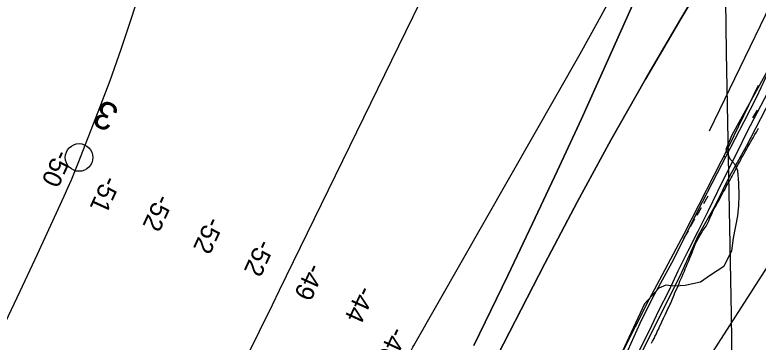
# Model space of a CAD drawing. Extents: x 3930721 to 3950824, y 220441 to 242861.
# Drawn here: x 3939511 to 3940855, y 227422 to 228013 of the extents above; entities that cross this region are included whole.
import ezdxf

# ---------------------------------------------------------------- set-up
doc = ezdxf.new("R2010")
doc.units = 0
for name, color, linetype in [('V-GRID-MAJR', 7, 'Continuous'), ('V-RIVR-EDGE', 7, 'Continuous'), ('V-RIVR-IDEN', 7, 'Continuous'), ('V-RIVR-JETY', 7, 'Continuous'), ('V-RIVR-MILE', 7, 'Continuous'), ('V-RIVR-RANG', 7, 'Continuous'), ('V-RRAP-FSHR', 7, 'Continuous'), ('V-TOPO-DPTH', 7, 'Continuous'), ('V-TOPO-MAJR', 7, 'Continuous'), ('V-TOPO-MINR', 7, 'Continuous'), ('V-TOPO-SHOR', 7, 'Continuous'), ('V-UTIL-LINE', 7, 'Continuous'), ('V-WETL-SWMP', 7, 'Continuous')]:
    doc.layers.add(name, color=color, linetype=linetype)

msp = doc.modelspace()

# ---------------------------------------------------------------- linework, layer by layer
at = {"layer": 'V-GRID-MAJR'}
msp.add_spline([(3940914.4, 221486.3), (3940866.3, 224158.2), (3940756.9, 230218.1), (3940647.6, 236278.1), (3940604.7, 238656.8)], degree=3, dxfattribs=at)
at = {"layer": 'V-RIVR-EDGE'}
msp.add_lwpolyline([(3940939, 228034.7), (3940807.6, 227796.2), (3940796.6, 227770.2), (3940803.6, 227753.6), (3940812.3, 227744.2), (3940817.8, 227732.4), (3940819.4, 227709.6), (3940820.2, 227687.5), (3940819.4, 227669.4), (3940817.8, 227650.5), (3940809.9, 227610.4), (3940806.8, 227587.6), (3940792.6, 227559.2), (3940769, 227543.5), (3940750.9, 227530.9), (3940723.3, 227524.6), (3940705.2, 227523.8), (3940687.9, 227525.4), (3940675.3, 227519.9), (3940649.4, 227491.5), (3940480.9, 227129.4)], dxfattribs=at)
at = {"layer": 'V-RIVR-JETY'}
for points in [[(3940975.3, 228056.9), (3940948.8, 227998.4), (3940919.5, 227941.1), (3940876.7, 227859.2), (3940833.1, 227775.8), (3940803.3, 227722), (3940777.1, 227669.1), (3940746.6, 227615.3), (3940716.2, 227548.1), (3940676.2, 227467.1), (3940639.1, 227394.4), (3940613.8, 227333.6), (3940588, 227284.2), (3940566.5, 227232.8), (3940530.6, 227163.6), (3940492.1, 227081.5), (3940457.5, 227003.6), (3940435.5, 226958.6), (3940412, 226909.2)], [(3940620.1, 227408.4), (3940641.6, 227456.9), (3940664.8, 227502.8), (3940702.6, 227572), (3940745.4, 227658.5), (3940780.9, 227726.9), (3940829.9, 227821), (3940852.6, 227865.7), (3940876.1, 227915.9)]]:
    msp.add_lwpolyline(points, dxfattribs=at)
at = {"layer": 'V-RIVR-MILE'}
msp.add_circle((3939627.5, 227755.9), 25, dxfattribs=at)
at = {"layer": 'V-RRAP-FSHR'}
msp.add_lwpolyline([(3940640.5, 227407.7), (3940658.5, 227443.6), (3940675.6, 227479.6), (3940693.8, 227515.6), (3940710.6, 227551.5), (3940728.5, 227587.3), (3940746.3, 227623.1), (3940764.7, 227658.9), (3940781.9, 227694.8), (3940799.7, 227730.6), (3940817.5, 227766.4), (3940835.3, 227802.2), (3940853.6, 227837.8), (3940872.3, 227873.3)], dxfattribs=at)
at = {"layer": 'V-TOPO-DPTH'}
for points in [[(3940340.8, 227416.1), (3940402.2, 227542.7), (3940447.3, 227636.8), (3940491.9, 227731.1), (3940535.5, 227825.8), (3940578.5, 227920.9), (3940734.2, 228269.4)], [(3940734.2, 228269.4), (3940578.5, 227920.9), (3940535.5, 227825.8), (3940491.9, 227731.1), (3940447.3, 227636.8), (3940402.2, 227542.7), (3940340.8, 227416.1)], [(3940816.6, 228175.7), (3940715.1, 228006.3), (3940651.1, 227897.2), (3940588.6, 227787.3), (3940528.1, 227676.2), (3940469.1, 227564.4), (3940362.4, 227357.4), (3940357, 227346.9), (3940351.8, 227336.5), (3940346.7, 227325.9), (3940341.6, 227315.3), (3940285, 227194.8), (3940251.8, 227123.8), (3940218.8, 227052.7), (3940186.1, 226981.6), (3940153.6, 226910.3), (3939964.5, 226493.2), (3939952.2, 226466), (3939939.8, 226438.8), (3939927.4, 226411.6), (3939914.9, 226384.5), (3939698.1, 225912.3)], [(3939570.3, 225876.8), (3939810.4, 226486.5), (3939910.3, 226761), (3939959.3, 226868.2), (3940009.4, 226974.8), (3940061.2, 227080.7), (3940114.1, 227186), (3940218.2, 227388.8), (3940219.9, 227392.3), (3940221.7, 227395.8), (3940223.4, 227399.2), (3940225.1, 227402.7), (3940226.9, 227406.2), (3940228.7, 227409.6), (3940230.5, 227413.1), (3940232.4, 227416.5), (3940533.1, 227943.2), (3940564.5, 227999.5), (3940595.1, 228056.1)], [(3939570.3, 225876.8), (3939810.4, 226486.5), (3939910.3, 226761), (3939959.3, 226868.2), (3940009.4, 226974.8), (3940061.2, 227080.7), (3940114.1, 227186), (3940218.2, 227388.8), (3940219.9, 227392.3), (3940221.7, 227395.8), (3940223.4, 227399.2), (3940225.1, 227402.7), (3940226.9, 227406.2), (3940228.7, 227409.6), (3940230.5, 227413.1), (3940232.4, 227416.5), (3940533.1, 227943.2), (3940564.5, 227999.5), (3940595.1, 228056.1)]]:
    msp.add_lwpolyline(points, dxfattribs=at)
at = {"layer": 'V-TOPO-MAJR'}
for points in [[(3939106.3, 225742.9), (3939376.3, 226272.7), (3939407.3, 226333.6), (3939438.1, 226394.6), (3939468.7, 226455.7), (3939499.2, 226516.8), (3939549.3, 226617.6), (3939554.7, 226628.4), (3939560, 226639.1), (3939565.3, 226649.9), (3939570.6, 226660.7), (3939717.3, 226961.4), (3939764.6, 227058.2), (3939812, 227155), (3939859.5, 227251.8), (3939907.1, 227348.6), (3939976.8, 227490.1), (3939989.5, 227516.1), (3940002.3, 227542), (3940015, 227568), (3940027.7, 227594), (3940294.5, 228140.7)], [(3939740.2, 228065.9), (3939722.1, 228008.4), (3939703.1, 227951.2), (3939682.8, 227894.5), (3939661.6, 227838), (3939625.4, 227745), (3939619.4, 227730), (3939613.2, 227715.1), (3939606.8, 227700.2), (3939600.1, 227685.5), (3939551.8, 227581), (3939520.6, 227514.1), (3939489.2, 227447.4)]]:
    msp.add_lwpolyline(points, dxfattribs=at)
at = {"layer": 'V-TOPO-MINR'}
for points in [[(3940766.8, 227803.9), (3940932.6, 228146.5), (3940939.7, 228161), (3940947, 228175.5), (3940954.4, 228189.9), (3940961.9, 228204.2), (3941144.3, 228546.7)], [(3940340.8, 227416.1), (3940402.2, 227542.7), (3940447.3, 227636.8), (3940491.9, 227731.1), (3940535.5, 227825.8), (3940578.5, 227920.9), (3940734.2, 228269.4)], [(3939698.1, 225912.3), (3939914.9, 226384.5), (3939927.4, 226411.6), (3939939.8, 226438.8), (3939952.2, 226466), (3939964.5, 226493.2), (3940153.6, 226910.3), (3940186.1, 226981.6), (3940218.8, 227052.7), (3940251.8, 227123.8), (3940285, 227194.8), (3940341.6, 227315.3), (3940346.7, 227325.9), (3940351.8, 227336.5), (3940357, 227346.9), (3940362.4, 227357.4), (3940469.1, 227564.4), (3940528.1, 227676.2), (3940588.6, 227787.3), (3940651.1, 227897.2), (3940715.1, 228006.3), (3940816.6, 228175.7)], [(3939570.3, 225876.8), (3939810.4, 226486.5), (3939910.3, 226761), (3939959.3, 226868.2), (3940009.4, 226974.8), (3940061.2, 227080.7), (3940114.1, 227186), (3940218.2, 227388.8), (3940219.9, 227392.3), (3940221.7, 227395.8), (3940223.4, 227399.2), (3940225.1, 227402.7), (3940226.9, 227406.2), (3940228.7, 227409.6), (3940230.5, 227413.1), (3940232.4, 227416.5), (3940533.1, 227943.2), (3940564.5, 227999.5), (3940595.1, 228056.1)]]:
    msp.add_lwpolyline(points, dxfattribs=at)
at = {"layer": 'V-TOPO-SHOR'}
for points in [[(3940776.5, 227665.3), (3940778.2, 227668.1), (3940781.3, 227673.8), (3940785.1, 227680.1), (3940786.8, 227683.6), (3940789.2, 227688.2), (3940791.2, 227692.4), (3940793, 227695.2), (3940795, 227698.7), (3940797.4, 227703.3), (3940799.1, 227706.5), (3940801.9, 227711.4), (3940803.6, 227714.5), (3940806.4, 227719.1), (3940807.7, 227722.3), (3940810.1, 227726.8), (3940812.5, 227731.1), (3940813.9, 227733.9), (3940815.9, 227738.1), (3940819.7, 227744.4), (3940821.1, 227747.2), (3940823.5, 227751.8), (3940824.9, 227755), (3940826.6, 227757.8), (3940829, 227761.6), (3940832.8, 227768.7), (3940834.5, 227771.5), (3940836.2, 227775.3), (3940839.6, 227781.3), (3940841.3, 227783.8), (3940843.4, 227788), (3940845.8, 227791.2), (3940849.2, 227797.5), (3940851.7, 227801.4), (3940853.7, 227805.2), (3940855.4, 227808.7)], [(3940662.1, 227420.3), (3940664.2, 227424.1), (3940666.9, 227429), (3940668.3, 227432.4), (3940671.1, 227437.7), (3940672.4, 227441.5), (3940675.2, 227446.7), (3940676.6, 227450.4), (3940678.9, 227455.2), (3940681, 227459.3), (3940684.1, 227465.9), (3940687.2, 227472.9), (3940689.9, 227478.1), (3940691.6, 227482.5), (3940693.3, 227485.5), (3940695.4, 227490.1), (3940696.8, 227492.8), (3940698.8, 227497.6), (3940699.9, 227500.6), (3940701.9, 227504.6), (3940703.3, 227507.7), (3940704.6, 227511.8), (3940707.7, 227518.5), (3940710.1, 227524.1), (3940712.2, 227528.6), (3940713.5, 227532.4), (3940715.9, 227537.6), (3940717.3, 227540.7), (3940719.3, 227545.9), (3940721.7, 227550.8), (3940723.1, 227554.7), (3940725.5, 227559.8), (3940726.8, 227563.3), (3940728.9, 227568.2), (3940730.3, 227571.2), (3940732.3, 227576.1), (3940734.7, 227581.3), (3940735.7, 227584.2), (3940737.1, 227587.7), (3940738.1, 227591.2), (3940739.5, 227594), (3940741.2, 227598.6), (3940742.5, 227601.7), (3940745.3, 227606.6), (3940748, 227611.6), (3940750.4, 227615.8), (3940752.1, 227618.6), (3940755.2, 227623.9), (3940759.4, 227629.5), (3940761.1, 227632), (3940762.8, 227635.5), (3940765.5, 227641.8), (3940767.6, 227646.4), (3940769, 227649.2), (3940771, 227653.7), (3940772.7, 227656.9), (3940775.1, 227661.8), (3940776.5, 227665.3)]]:
    msp.add_lwpolyline(points, dxfattribs=at)
at = {"layer": 'V-UTIL-LINE'}
msp.add_lwpolyline([(3947453.8, 235874.4), (3945931.1, 235655.1), (3945509.1, 234777.7), (3940428.6, 226869.1), (3939084.6, 223621.7)], dxfattribs=at)
at = {"layer": 'V-WETL-SWMP'}
for p, q in [((3940852.9, 227841.2), (3940845, 227827.3)), ((3940792.6, 227758.6), (3940796, 227756.7)), ((3940764, 227685.9), (3940756, 227672)), ((3940752, 227665.1), (3940744.1, 227651.2)), ((3940740.1, 227644.3), (3940732.2, 227630.4)), ((3940728.2, 227623.4), (3940720.2, 227609.6))]:
    msp.add_line(p, q, dxfattribs=at)
for points in [[(3940854.9, 227885.8), (3940801.7, 227776.3), (3940720.6, 227617.7), (3940657.5, 227498.7), (3940607.6, 227400.2)], [(3940728.9, 227568.2), (3940730.3, 227571.2), (3940732.3, 227576.1), (3940734.7, 227581.3), (3940735.7, 227584.2), (3940737.1, 227587.7), (3940738.1, 227591.2), (3940739.5, 227594), (3940741.2, 227598.6), (3940742.5, 227601.7), (3940748, 227611.6), (3940750.4, 227615.8), (3940752.1, 227618.6), (3940755.2, 227623.9), (3940759.4, 227629.5), (3940761.1, 227632), (3940762.8, 227635.5), (3940765.5, 227641.8), (3940767.6, 227646.4), (3940769, 227649.2), (3940771, 227653.7), (3940772.7, 227656.9), (3940775.1, 227661.8), (3940776.5, 227665.3), (3940778.2, 227668.1), (3940781.3, 227673.8), (3940785.1, 227680.1), (3940786.8, 227683.6), (3940789.2, 227688.2), (3940791.2, 227692.4), (3940793, 227695.2), (3940795, 227698.7), (3940797.4, 227703.3), (3940799.1, 227706.5), (3940801.9, 227711.4), (3940803.6, 227714.5), (3940806.4, 227719.1), (3940807.7, 227722.3), (3940810.1, 227726.8), (3940812.5, 227731.1), (3940815.9, 227738.1), (3940819.7, 227744.4), (3940821.1, 227747.2), (3940823.5, 227751.8), (3940824.9, 227755), (3940826.6, 227757.8), (3940829, 227761.6), (3940832.8, 227768.7), (3940834.5, 227771.5), (3940836.2, 227775.3), (3940839.6, 227781.3), (3940841.3, 227783.8), (3940843.4, 227788), (3940845.8, 227791.2), (3940849.2, 227797.5), (3940851.7, 227801.4), (3940853.7, 227805.2), (3940855.4, 227808.7)], [(3940662.1, 227420.3), (3940664.2, 227424.1), (3940666.9, 227429), (3940668.3, 227432.4), (3940671.1, 227437.7), (3940672.4, 227441.5), (3940675.2, 227446.7), (3940676.6, 227450.4), (3940678.9, 227455.2), (3940681, 227459.3), (3940684.1, 227465.9), (3940687.2, 227472.9), (3940689.9, 227478.1), (3940691.6, 227482.5), (3940693.3, 227485.5), (3940695.4, 227490.1), (3940696.8, 227492.8), (3940698.8, 227497.6), (3940699.9, 227500.6), (3940701.9, 227504.6), (3940703.3, 227507.7), (3940704.6, 227511.8), (3940707.7, 227518.5), (3940710.1, 227524.1), (3940712.2, 227528.6), (3940713.5, 227532.4), (3940715.9, 227537.6), (3940717.3, 227540.7), (3940719.3, 227545.9), (3940721.7, 227550.8), (3940723.1, 227554.7), (3940725.5, 227559.8), (3940726.8, 227563.3), (3940728.9, 227568.2)]]:
    msp.add_lwpolyline(points, dxfattribs=at)

# ---------------------------------------------------------------- texts
at = {"layer": 'V-RIVR-IDEN'}
msp.add_text('3', height=50, rotation=155.0998, dxfattribs=at).set_placement((3939702.7, 227846.1))
at = {"layer": 'V-RIVR-RANG'}
for s, rotation, p in [('-50', 245.4983, (3939585.7, 227771.9)), ('-51', 245.4983, (3939673, 227725)), ('-52', 245.4983, (3939768.4, 227691.7)), ('-52', 245.4983, (3939859.8, 227651)), ('-52', 245.4983, (3939951.5, 227610.3)), ('-49', 245.4983, (3940042.3, 227567.1)), ('-44', 245.4983, (3940133.8, 227526.4)), ('-46', 245.3583, (3940192.1, 227452.4))]:
    msp.add_text(s, height=33.5, rotation=rotation, dxfattribs=at).set_placement(p)

doc.saveas('drawing.dxf')
